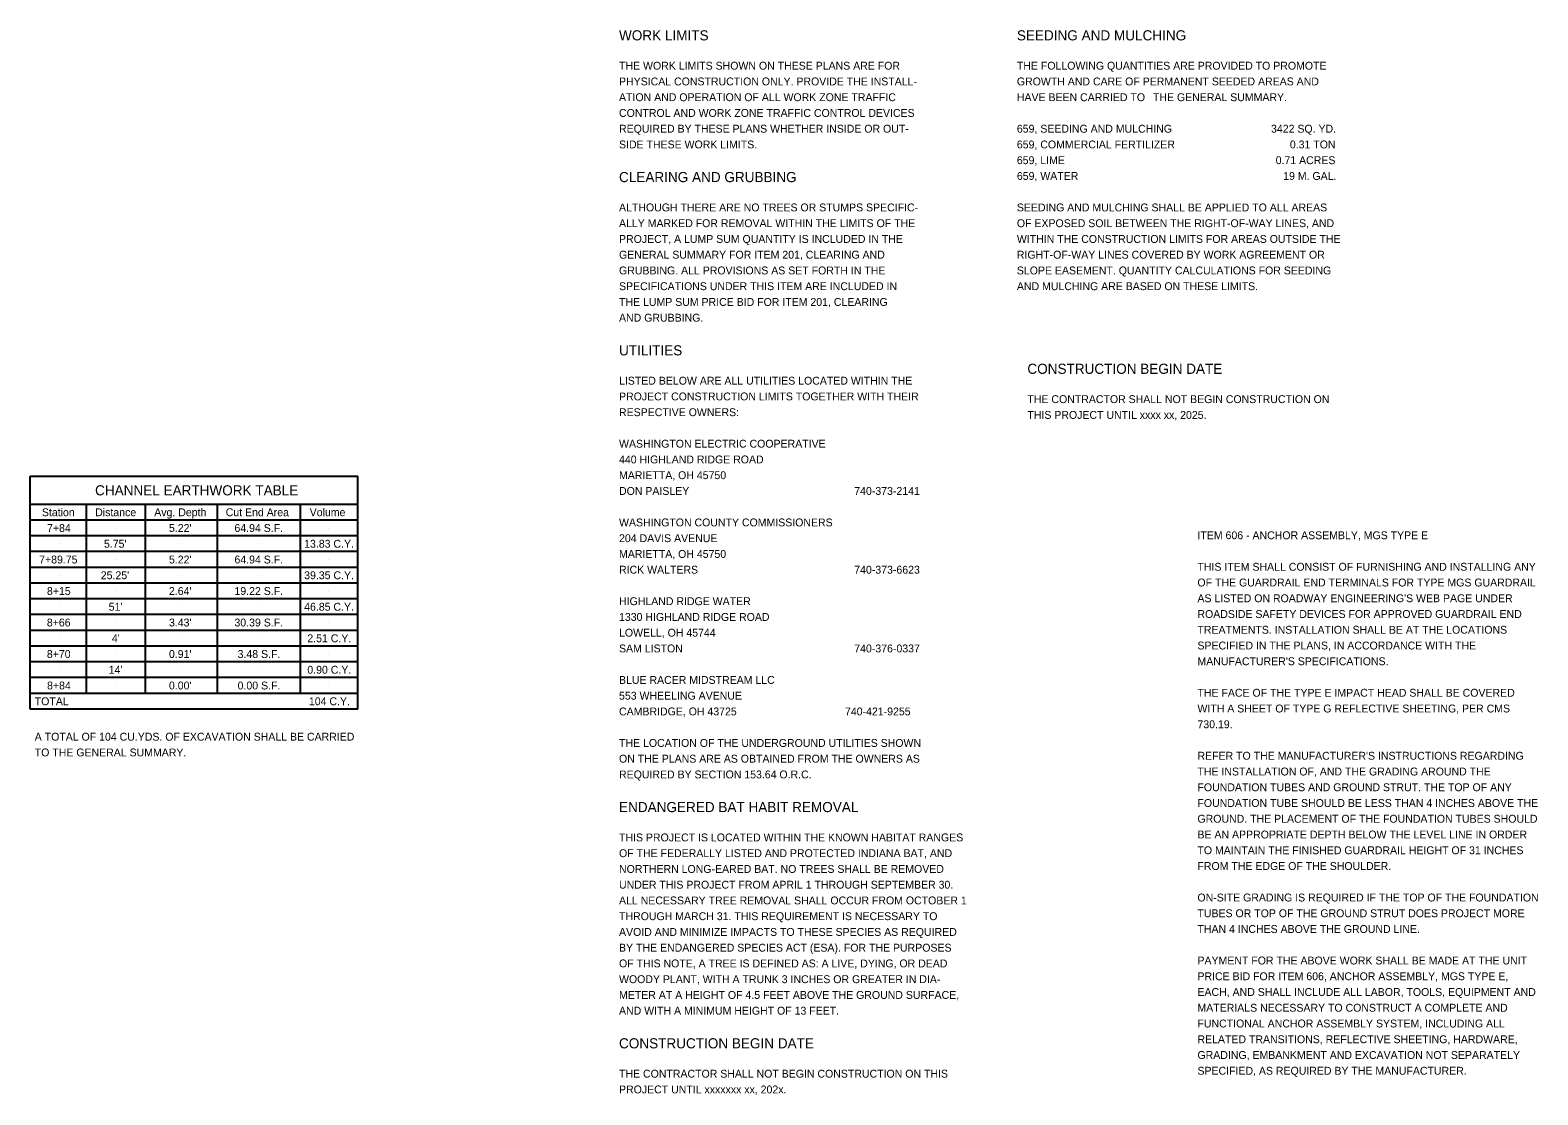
# Model space of a CAD drawing. Extents: x -30 to 76, y -31 to 50.
# Drawn here: x -30.37 to -3.58, y 0.08 to 19.01 of the extents above; entities that cross this region are included whole.
import ezdxf

# ---------------------------------------------------------------- set-up
doc = ezdxf.new("R2010")
doc.units = 0
doc.layers.add('SH_Data', color=7, linetype='Continuous')
doc.layers.add('SH_Text', color=7, linetype='Continuous')

msp = doc.modelspace()

# ---------------------------------------------------------------- linework, layer by layer
at = {"layer": 'SH_Data'}
for p, q in [((-30.374, 6.94), (-30.374, 11.08)), ((-30.374, 11.08), (-24.552, 11.08)), ((-24.552, 6.94), (-24.552, 11.08)), ((-24.552, 10.58), (-30.374, 10.58)), ((-29.375, 7.22), (-29.375, 10.58)), ((-28.324, 7.22), (-28.324, 10.58)), ((-27.043, 7.22), (-27.043, 10.58)), ((-25.572, 7.22), (-25.572, 10.58)), ((-24.552, 10.3), (-30.374, 10.3)), ((-29.855, 10.44), (-29.855, 10.44)), ((-28.84, 10.44), (-28.84, 10.44)), ((-27.684, 10.44), (-27.684, 10.44)), ((-26.322, 10.44), (-26.322, 10.44)), ((-25.072, 10.44), (-25.072, 10.44)), ((-24.552, 10.02), (-30.374, 10.02)), ((-29.855, 10.16), (-29.855, 10.16)), ((-28.84, 10.16), (-28.84, 10.16)), ((-27.684, 10.16), (-27.684, 10.16)), ((-26.322, 10.16), (-26.322, 10.16)), ((-25.072, 10.16), (-25.072, 10.16)), ((-24.552, 9.74), (-30.374, 9.74)), ((-29.855, 9.88), (-29.855, 9.88)), ((-28.84, 9.88), (-28.84, 9.88)), ((-27.684, 9.88), (-27.684, 9.88)), ((-26.322, 9.88), (-26.322, 9.88)), ((-25.072, 9.88), (-25.072, 9.88)), ((-24.552, 9.46), (-30.374, 9.46)), ((-29.855, 9.6), (-29.855, 9.6)), ((-28.84, 9.6), (-28.84, 9.6)), ((-27.684, 9.6), (-27.684, 9.6)), ((-26.322, 9.6), (-26.322, 9.6)), ((-25.072, 9.6), (-25.072, 9.6)), ((-24.552, 9.18), (-30.374, 9.18)), ((-29.855, 9.32), (-29.855, 9.32)), ((-28.84, 9.32), (-28.84, 9.32)), ((-27.684, 9.32), (-27.684, 9.32)), ((-26.322, 9.32), (-26.322, 9.32)), ((-25.072, 9.32), (-25.072, 9.32)), ((-24.552, 8.9), (-30.374, 8.9)), ((-29.855, 9.04), (-29.855, 9.04)), ((-28.84, 9.04), (-28.84, 9.04)), ((-27.684, 9.04), (-27.684, 9.04)), ((-26.322, 9.04), (-26.322, 9.04)), ((-25.072, 9.04), (-25.072, 9.04)), ((-24.552, 8.62), (-30.374, 8.62)), ((-29.855, 8.76), (-29.855, 8.76)), ((-28.84, 8.76), (-28.84, 8.76)), ((-27.684, 8.76), (-27.684, 8.76)), ((-26.322, 8.76), (-26.322, 8.76)), ((-25.072, 8.76), (-25.072, 8.76)), ((-24.552, 8.34), (-30.374, 8.34)), ((-29.855, 8.48), (-29.855, 8.48)), ((-28.84, 8.48), (-28.84, 8.48)), ((-27.684, 8.48), (-27.684, 8.48)), ((-26.322, 8.48), (-26.322, 8.48)), ((-25.072, 8.48), (-25.072, 8.48)), ((-24.552, 8.06), (-30.374, 8.06)), ((-29.855, 8.2), (-29.855, 8.2)), ((-28.84, 8.2), (-28.84, 8.2)), ((-27.684, 8.2), (-27.684, 8.2)), ((-26.322, 8.2), (-26.322, 8.2)), ((-25.072, 8.2), (-25.072, 8.2)), ((-24.552, 7.78), (-30.374, 7.78)), ((-29.855, 7.92), (-29.855, 7.92)), ((-28.84, 7.92), (-28.84, 7.92)), ((-27.684, 7.92), (-27.684, 7.92)), ((-26.322, 7.92), (-26.322, 7.92)), ((-25.072, 7.92), (-25.072, 7.92)), ((-29.855, 7.64), (-29.855, 7.64)), ((-28.84, 7.64), (-28.84, 7.64)), ((-27.684, 7.64), (-27.684, 7.64)), ((-26.322, 7.64), (-26.322, 7.64)), ((-25.072, 7.64), (-25.072, 7.64)), ((-24.552, 7.5), (-30.374, 7.5)), ((-29.855, 7.36), (-29.855, 7.36)), ((-28.84, 7.36), (-28.84, 7.36)), ((-27.684, 7.36), (-27.684, 7.36)), ((-26.322, 7.36), (-26.322, 7.36)), ((-25.072, 7.36), (-25.072, 7.36)), ((-24.552, 7.22), (-30.374, 7.22)), ((-24.552, 6.94), (-30.374, 6.94))]:
    msp.add_line(p, q, dxfattribs=at)

# ---------------------------------------------------------------- texts
for s, height, p in [('CHANNEL EARTHWORK TABLE', 0.18, (-29.22, 10.74)), ('Station', 0.14, (-30.165, 10.37)), ('Distance', 0.14, (-29.218, 10.37)), ('Avg. Depth', 0.14, (-28.168, 10.37)), ('Cut End Area', 0.14, (-26.898, 10.37)), ('Volume', 0.14, (-25.406, 10.37)), ('7+84', 0.14, (-30.073, 10.09)), ("5.22'", 0.14, (-27.907, 10.09)), ('64.94 S.F.', 0.14, (-26.743, 10.09)), ("5.75'", 0.14, (-29.062, 9.81)), ('13.83 C.Y.', 0.14, (-25.504, 9.81)), ('7+89.75', 0.14, (-30.214, 9.53)), ("5.22'", 0.14, (-27.907, 9.53)), ('64.94 S.F.', 0.14, (-26.743, 9.53)), ("25.25'", 0.14, (-29.118, 9.25)), ('39.35 C.Y.', 0.14, (-25.504, 9.25)), ('8+15', 0.14, (-30.075, 8.97)), ("2.64'", 0.14, (-27.907, 8.97)), ('19.22 S.F.', 0.14, (-26.743, 8.97)), ("51'", 0.14, (-28.978, 8.69)), ('46.85 C.Y.', 0.14, (-25.504, 8.69)), ('8+66', 0.14, (-30.077, 8.41)), ("3.43'", 0.14, (-27.907, 8.41)), ('30.39 S.F.', 0.14, (-26.743, 8.41)), ("4'", 0.14, (-28.922, 8.13)), ('2.51 C.Y.', 0.14, (-25.448, 8.13)), ('8+70', 0.14, (-30.077, 7.85)), ("0.91'", 0.14, (-27.907, 7.85)), ('3.48 S.F.', 0.14, (-26.687, 7.85)), ("14'", 0.14, (-28.978, 7.57)), ('0.90 C.Y.', 0.14, (-25.448, 7.57)), ('8+84', 0.14, (-30.073, 7.29)), ("0.00'", 0.14, (-27.907, 7.29)), ('0.00 S.F.', 0.14, (-26.687, 7.29)), ('TOTAL', 0.14, (-30.292, 7.01)), ('104 C.Y.', 0.14, (-25.42, 7.01))]:
    msp.add_text(s, height=height, dxfattribs=at).set_placement(p)
at = {"layer": 'SH_Text'}
for s, height, p in [('WORK LIMITS', 0.18, (-19.909, 18.829)), ('SEEDING AND MULCHING', 0.18, (-12.839, 18.829)), ('THE WORK LIMITS SHOWN ON THESE PLANS ARE FOR', 0.14, (-19.909, 18.309)), ('THE FOLLOWING QUANTITIES ARE PROVIDED TO PROMOTE', 0.14, (-12.839, 18.309)), ('PHYSICAL CONSTRUCTION ONLY. PROVIDE THE INSTALL-', 0.14, (-19.909, 18.029)), ('GROWTH AND CARE OF PERMANENT SEEDED AREAS AND', 0.14, (-12.839, 18.029)), ('ATION AND OPERATION OF ALL WORK ZONE TRAFFIC', 0.14, (-19.909, 17.749)), ('HAVE BEEN CARRIED TO', 0.14, (-12.839, 17.749)), (' THE GENERAL SUMMARY.', 0.14, (-10.473, 17.749)), ('CONTROL AND WORK ZONE TRAFFIC CONTROL DEVICES', 0.14, (-19.909, 17.469)), ('REQUIRED BY THESE PLANS WHETHER INSIDE OR OUT-', 0.14, (-19.909, 17.189)), ('659, SEEDING AND MULCHING', 0.14, (-12.839, 17.189)), ('3422 SQ. YD.', 0.14, (-8.322, 17.189)), ('SIDE THESE WORK LIMITS.', 0.14, (-19.909, 16.909)), ('659, COMMERCIAL FERTILIZER', 0.14, (-12.839, 16.909)), (' 0.31 TON', 0.14, (-8.04, 16.909)), ('659, LIME', 0.14, (-12.839, 16.629)), (' 0.71 ACRES', 0.14, (-8.292, 16.629)), ('CLEARING AND GRUBBING', 0.18, (-19.909, 16.309)), ('659, WATER', 0.14, (-12.839, 16.349)), (' 19 M. GAL.', 0.14, (-8.159, 16.349)), ('ALTHOUGH THERE ARE NO TREES OR STUMPS SPECIFIC-', 0.14, (-19.909, 15.789)), ('SEEDING AND MULCHING SHALL BE APPLIED TO ALL AREAS', 0.14, (-12.839, 15.789)), ('ALLY MARKED FOR REMOVAL WITHIN THE LIMITS OF THE', 0.14, (-19.909, 15.509)), ('OF EXPOSED SOIL BETWEEN THE RIGHT-OF-WAY LINES, AND', 0.14, (-12.839, 15.509)), ('PROJECT, A LUMP SUM QUANTITY IS INCLUDED IN THE', 0.14, (-19.909, 15.229)), ('WITHIN THE CONSTRUCTION LIMITS FOR AREAS OUTSIDE THE', 0.14, (-12.839, 15.229)), ('GENERAL SUMMARY FOR ITEM 201, CLEARING AND', 0.14, (-19.909, 14.949)), ('RIGHT-OF-WAY LINES COVERED BY WORK AGREEMENT OR', 0.14, (-12.839, 14.949)), ('GRUBBING. ALL PROVISIONS AS SET FORTH IN THE', 0.14, (-19.909, 14.669)), ('SLOPE EASEMENT. QUANTITY CALCULATIONS FOR SEEDING', 0.14, (-12.839, 14.669)), ('SPECIFICATIONS UNDER THIS ITEM ARE INCLUDED IN', 0.14, (-19.909, 14.389)), ('AND MULCHING ARE BASED ON THESE LIMITS.', 0.14, (-12.839, 14.389)), ('THE LUMP SUM PRICE BID FOR ITEM 201, CLEARING', 0.14, (-19.909, 14.109)), ('AND GRUBBING.', 0.14, (-19.909, 13.829)), ('UTILITIES', 0.18, (-19.909, 13.229)), ('CONSTRUCTION BEGIN DATE', 0.18, (-12.652, 12.901)), ('LISTED BELOW ARE ALL UTILITIES LOCATED WITHIN THE', 0.14, (-19.909, 12.709)), ('PROJECT CONSTRUCTION LIMITS TOGETHER WITH THEIR', 0.14, (-19.909, 12.429)), ('THE CONTRACTOR SHALL NOT BEGIN CONSTRUCTION ON', 0.14, (-12.652, 12.381)), ('RESPECTIVE OWNERS:', 0.14, (-19.909, 12.149)), ('THIS PROJECT UNTIL xxxx xx, 2025.', 0.14, (-12.652, 12.101)), ('WASHINGTON ELECTRIC COOPERATIVE', 0.14, (-19.909, 11.589)), ('440 HIGHLAND RIDGE ROAD', 0.14, (-19.909, 11.309)), ('MARIETTA, OH 45750', 0.14, (-19.909, 11.029)), ('DON PAISLEY', 0.14, (-19.909, 10.749)), ('     740-373-2141', 0.14, (-15.989, 10.749)), ('WASHINGTON COUNTY COMMISSIONERS', 0.14, (-19.909, 10.189)), ('204 DAVIS AVENUE', 0.14, (-19.909, 9.909)), ('ITEM 606 - ANCHOR ASSEMBLY, MGS TYPE E', 0.14, (-9.63, 9.961)), ('MARIETTA, OH 45750', 0.14, (-19.909, 9.629)), ('RICK WALTERS', 0.14, (-19.909, 9.349)), ('     740-373-6623', 0.14, (-15.989, 9.349)), ('THIS ITEM SHALL CONSIST OF FURNISHING AND INSTALLING ANY', 0.14, (-9.63, 9.401)), ('OF THE GUARDRAIL END TERMINALS FOR TYPE MGS GUARDRAIL', 0.14, (-9.63, 9.121)), ('HIGHLAND RIDGE WATER', 0.14, (-19.909, 8.789)), ("AS LISTED ON ROADWAY ENGINEERING'S WEB PAGE UNDER", 0.14, (-9.63, 8.841)), ('1330 HIGHLAND RIDGE ROAD', 0.14, (-19.909, 8.509)), ('ROADSIDE SAFETY DEVICES FOR APPROVED GUARDRAIL END', 0.14, (-9.63, 8.561)), ('LOWELL, OH 45744', 0.14, (-19.909, 8.229)), ('TREATMENTS. INSTALLATION SHALL BE AT THE LOCATIONS', 0.14, (-9.63, 8.281)), ('SAM LISTON', 0.14, (-19.909, 7.949)), ('     740-376-0337', 0.14, (-15.989, 7.949)), ('SPECIFIED IN THE PLANS, IN ACCORDANCE WITH THE', 0.14, (-9.63, 8.001)), ("MANUFACTURER'S SPECIFICATIONS.", 0.14, (-9.63, 7.721)), ('BLUE RACER MIDSTREAM LLC', 0.14, (-19.909, 7.389)), ('553 WHEELING AVENUE', 0.14, (-19.909, 7.109)), ('THE FACE OF THE TYPE E IMPACT HEAD SHALL BE COVERED', 0.14, (-9.63, 7.161)), ('CAMBRIDGE, OH 43725                                     740-421-9255', 0.14, (-19.909, 6.829)), ('WITH A SHEET OF TYPE G REFLECTIVE SHEETING, PER CMS', 0.14, (-9.63, 6.881)), ('730.19.', 0.14, (-9.63, 6.601)), ('A TOTAL OF 104 CU.YDS. OF EXCAVATION SHALL BE CARRIED', 0.14, (-30.292, 6.38)), ('TO THE GENERAL SUMMARY.', 0.14, (-30.292, 6.1)), ('THE LOCATION OF THE UNDERGROUND UTILITIES SHOWN', 0.14, (-19.909, 6.269)), ("REFER TO THE MANUFACTURER'S INSTRUCTIONS REGARDING", 0.14, (-9.63, 6.041)), ('ON THE PLANS ARE AS OBTAINED FROM THE OWNERS AS', 0.14, (-19.909, 5.989)), ('THE INSTALLATION OF, AND THE GRADING AROUND THE', 0.14, (-9.63, 5.761)), ('REQUIRED BY SECTION 153.64 O.R.C.', 0.14, (-19.909, 5.709)), ('FOUNDATION TUBES AND GROUND STRUT. THE TOP OF ANY', 0.14, (-9.63, 5.481)), ('ENDANGERED BAT HABIT REMOVAL', 0.18, (-19.909, 5.109)), ('FOUNDATION TUBE SHOULD BE LESS THAN 4 INCHES ABOVE THE', 0.14, (-9.63, 5.201)), ('GROUND. THE PLACEMENT OF THE FOUNDATION TUBES SHOULD', 0.14, (-9.63, 4.921)), ('THIS PROJECT IS LOCATED WITHIN THE KNOWN HABITAT RANGES', 0.14, (-19.909, 4.589)), ('BE AN APPROPRIATE DEPTH BELOW THE LEVEL LINE IN ORDER', 0.14, (-9.63, 4.641)), ('OF THE FEDERALLY LISTED AND PROTECTED INDIANA BAT, AND', 0.14, (-19.909, 4.309)), ('TO MAINTAIN THE FINISHED GUARDRAIL HEIGHT OF 31 INCHES', 0.14, (-9.63, 4.361)), ('NORTHERN LONG-EARED BAT. NO TREES SHALL BE REMOVED', 0.14, (-19.909, 4.029)), ('FROM THE EDGE OF THE SHOULDER.', 0.14, (-9.63, 4.081)), ('UNDER THIS PROJECT FROM APRIL 1 THROUGH SEPTEMBER 30.', 0.14, (-19.909, 3.749)), ('ALL NECESSARY TREE REMOVAL SHALL OCCUR FROM OCTOBER 1', 0.14, (-19.909, 3.469)), ('ON-SITE GRADING IS REQUIRED IF THE TOP OF THE FOUNDATION', 0.14, (-9.63, 3.521)), ('THROUGH MARCH 31. THIS REQUIREMENT IS NECESSARY TO', 0.14, (-19.909, 3.189)), ('TUBES OR TOP OF THE GROUND STRUT DOES PROJECT MORE', 0.14, (-9.63, 3.241)), ('AVOID AND MINIMIZE IMPACTS TO THESE SPECIES AS REQUIRED', 0.14, (-19.909, 2.909)), ('THAN 4 INCHES ABOVE THE GROUND LINE.', 0.14, (-9.63, 2.961)), ('BY THE ENDANGERED SPECIES ACT (ESA). FOR THE PURPOSES', 0.14, (-19.909, 2.629)), ('OF THIS NOTE, A TREE IS DEFINED AS: A LIVE, DYING, OR DEAD', 0.14, (-19.909, 2.349)), ('PAYMENT FOR THE ABOVE WORK SHALL BE MADE AT THE UNIT', 0.14, (-9.63, 2.401)), ('WOODY PLANT, WITH A TRUNK 3 INCHES OR GREATER IN DIA-', 0.14, (-19.909, 2.069)), ('PRICE BID FOR ITEM 606, ANCHOR ASSEMBLY, MGS TYPE E,', 0.14, (-9.63, 2.121)), ('METER AT A HEIGHT OF 4.5 FEET ABOVE THE GROUND SURFACE,', 0.14, (-19.909, 1.789)), ('EACH, AND SHALL INCLUDE ALL LABOR, TOOLS, EQUIPMENT AND', 0.14, (-9.63, 1.841)), ('AND WITH A MINIMUM HEIGHT OF 13 FEET.', 0.14, (-19.909, 1.509)), ('MATERIALS NECESSARY TO CONSTRUCT A COMPLETE AND', 0.14, (-9.63, 1.561)), ('FUNCTIONAL ANCHOR ASSEMBLY SYSTEM, INCLUDING ALL', 0.14, (-9.63, 1.281)), ('CONSTRUCTION BEGIN DATE', 0.18, (-19.909, 0.909)), ('RELATED TRANSITIONS, REFLECTIVE SHEETING, HARDWARE,', 0.14, (-9.63, 1.001)), ('GRADING, EMBANKMENT AND EXCAVATION NOT SEPARATELY', 0.14, (-9.63, 0.721)), ('SPECIFIED, AS REQUIRED BY THE MANUFACTURER.', 0.14, (-9.63, 0.441)), ('THE CONTRACTOR SHALL NOT BEGIN CONSTRUCTION ON THIS', 0.14, (-19.909, 0.389)), ('PROJECT UNTIL xxxxxxx xx, 202x.', 0.14, (-19.909, 0.109))]:
    msp.add_text(s, height=height, dxfattribs=at).set_placement(p)

doc.saveas('drawing.dxf')
